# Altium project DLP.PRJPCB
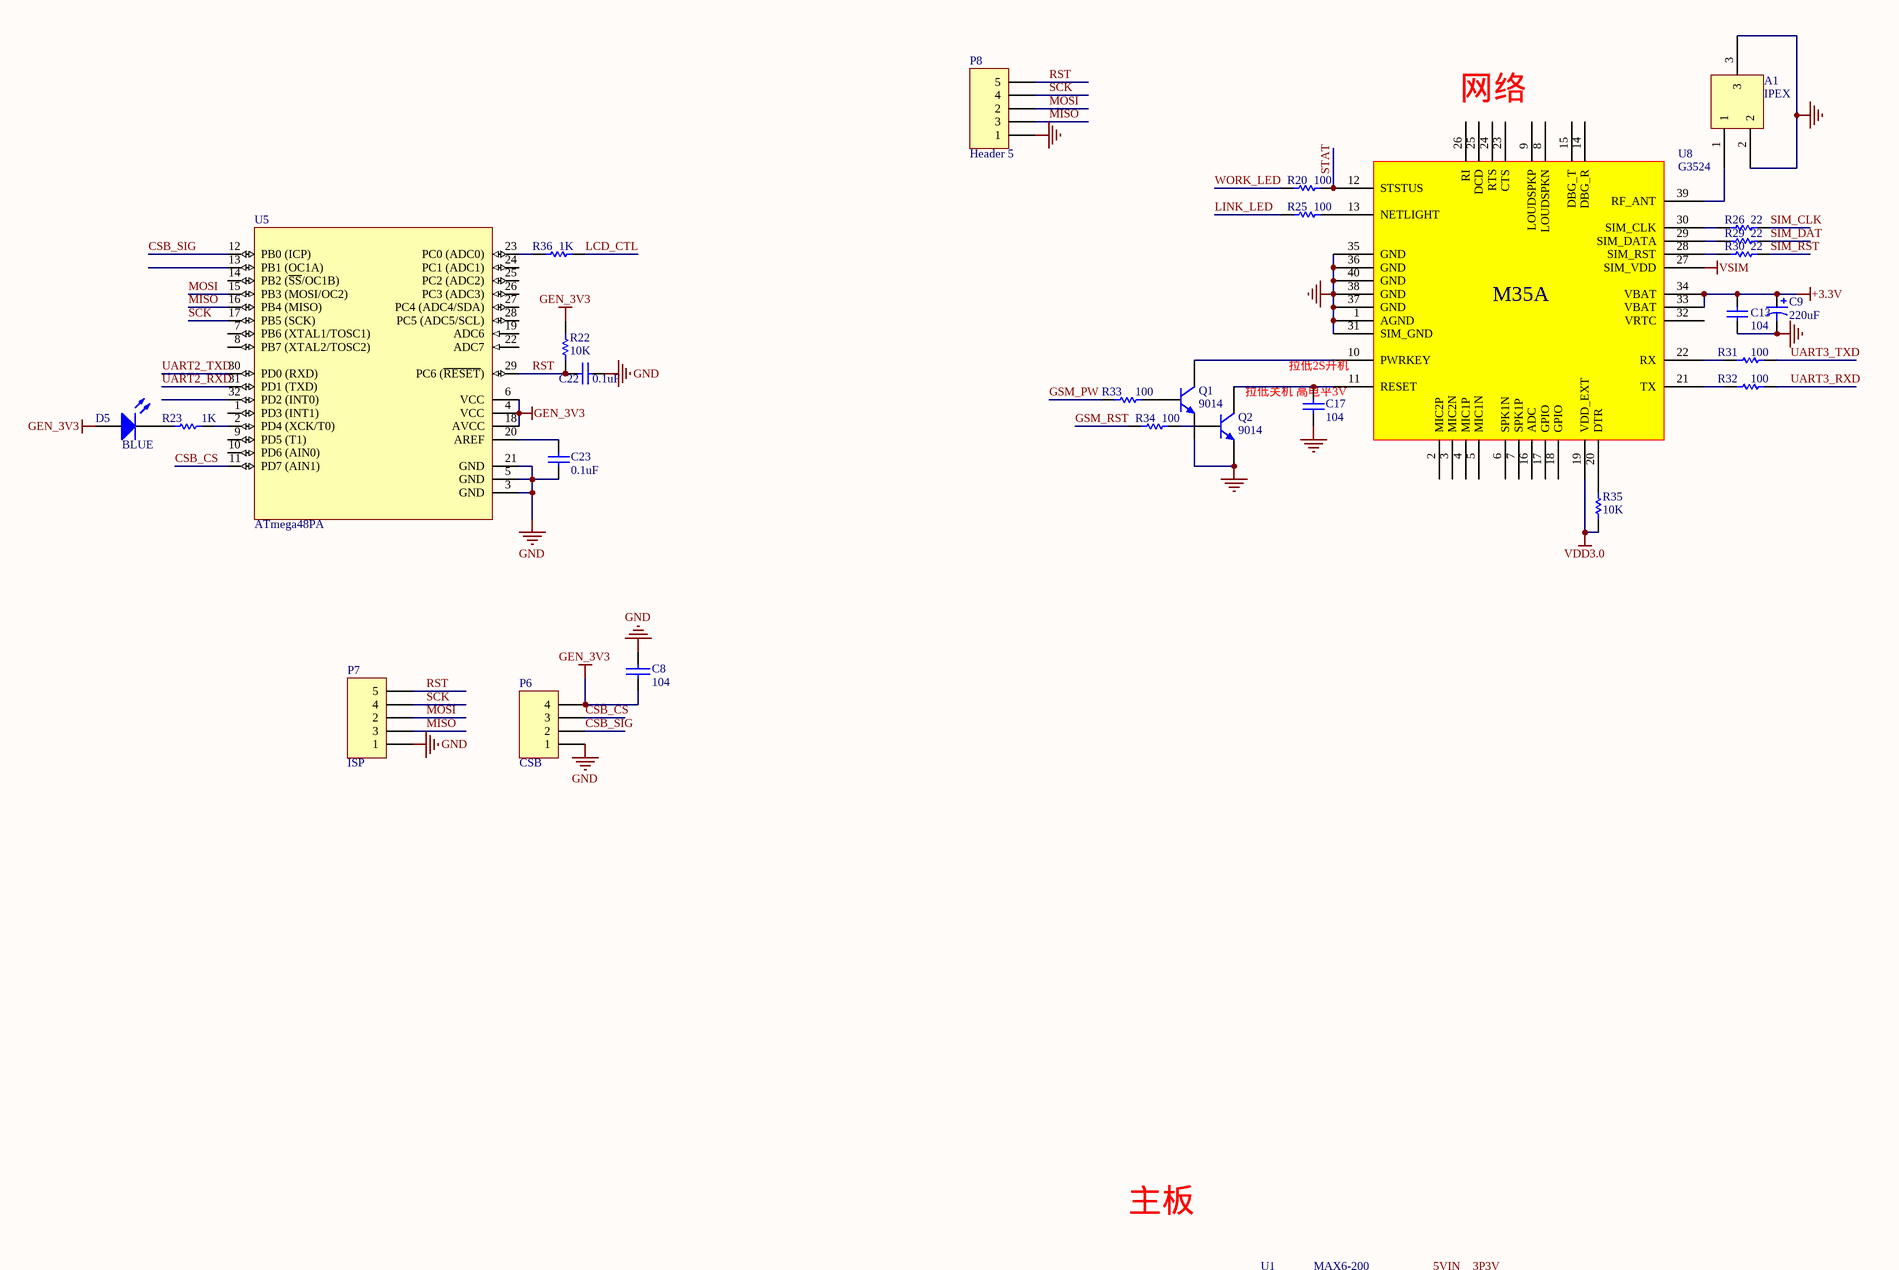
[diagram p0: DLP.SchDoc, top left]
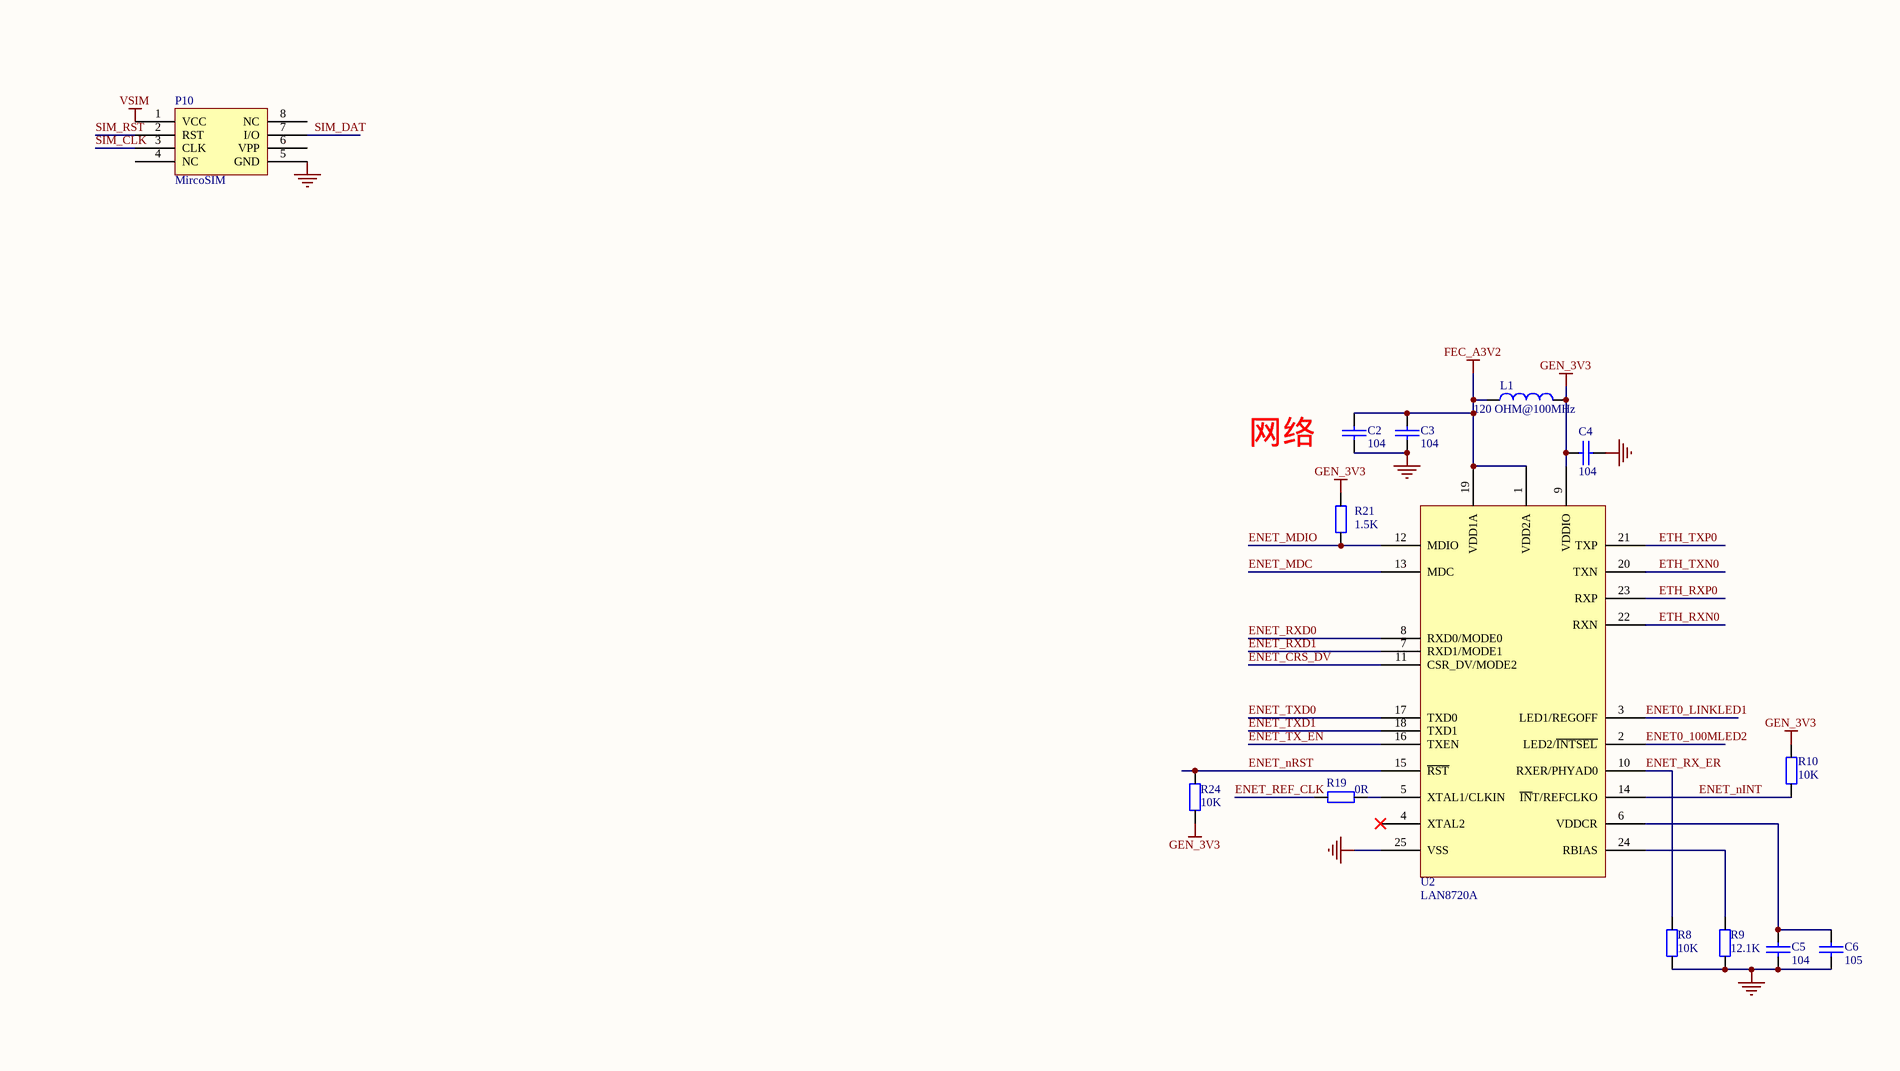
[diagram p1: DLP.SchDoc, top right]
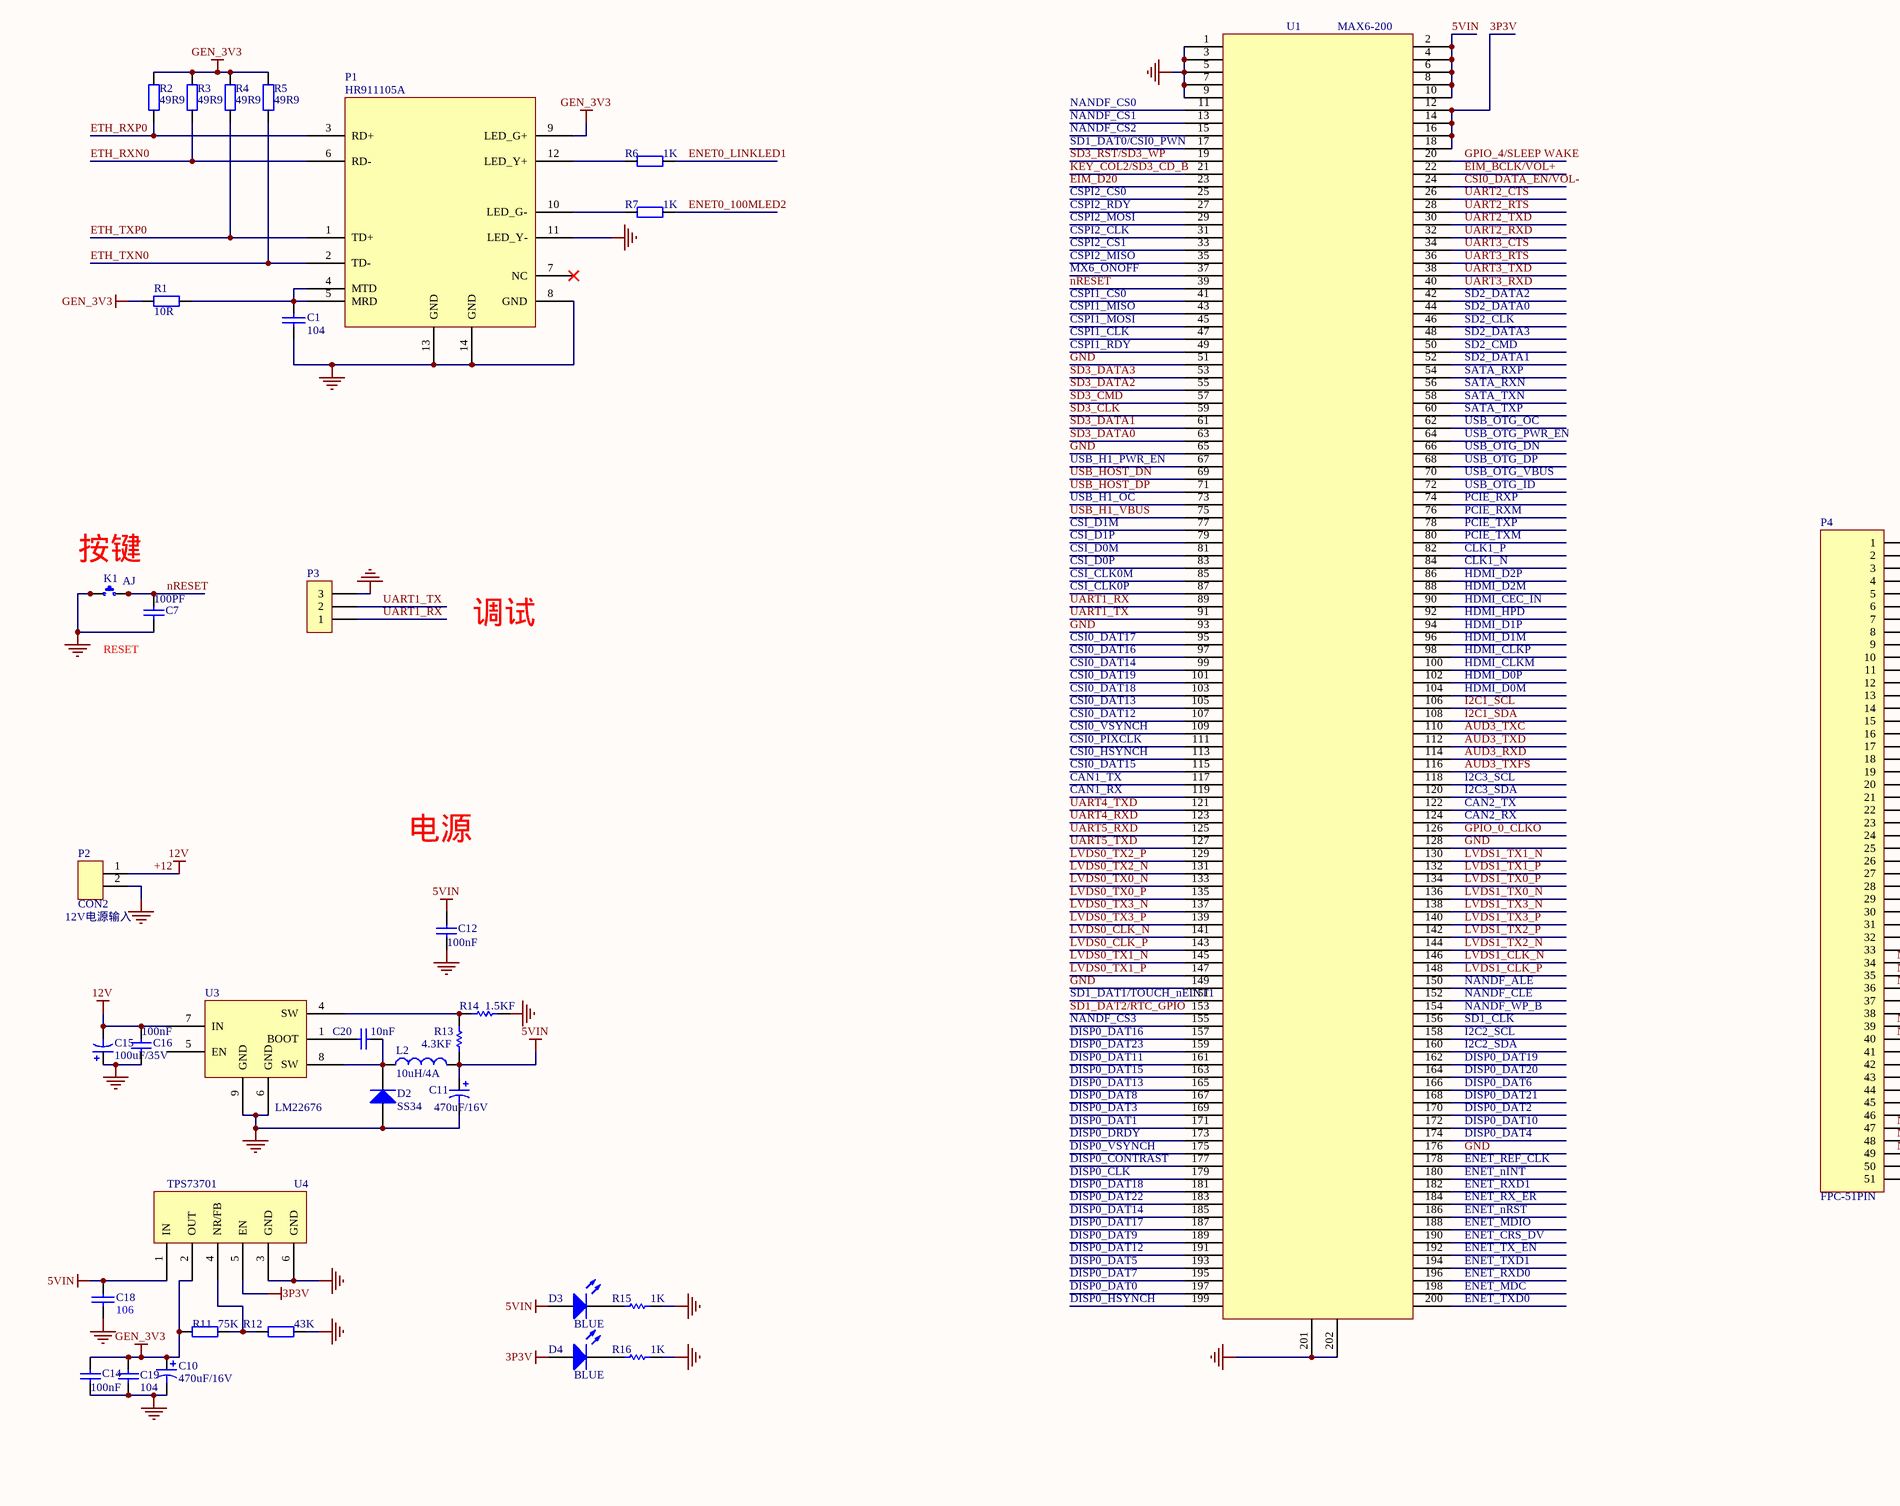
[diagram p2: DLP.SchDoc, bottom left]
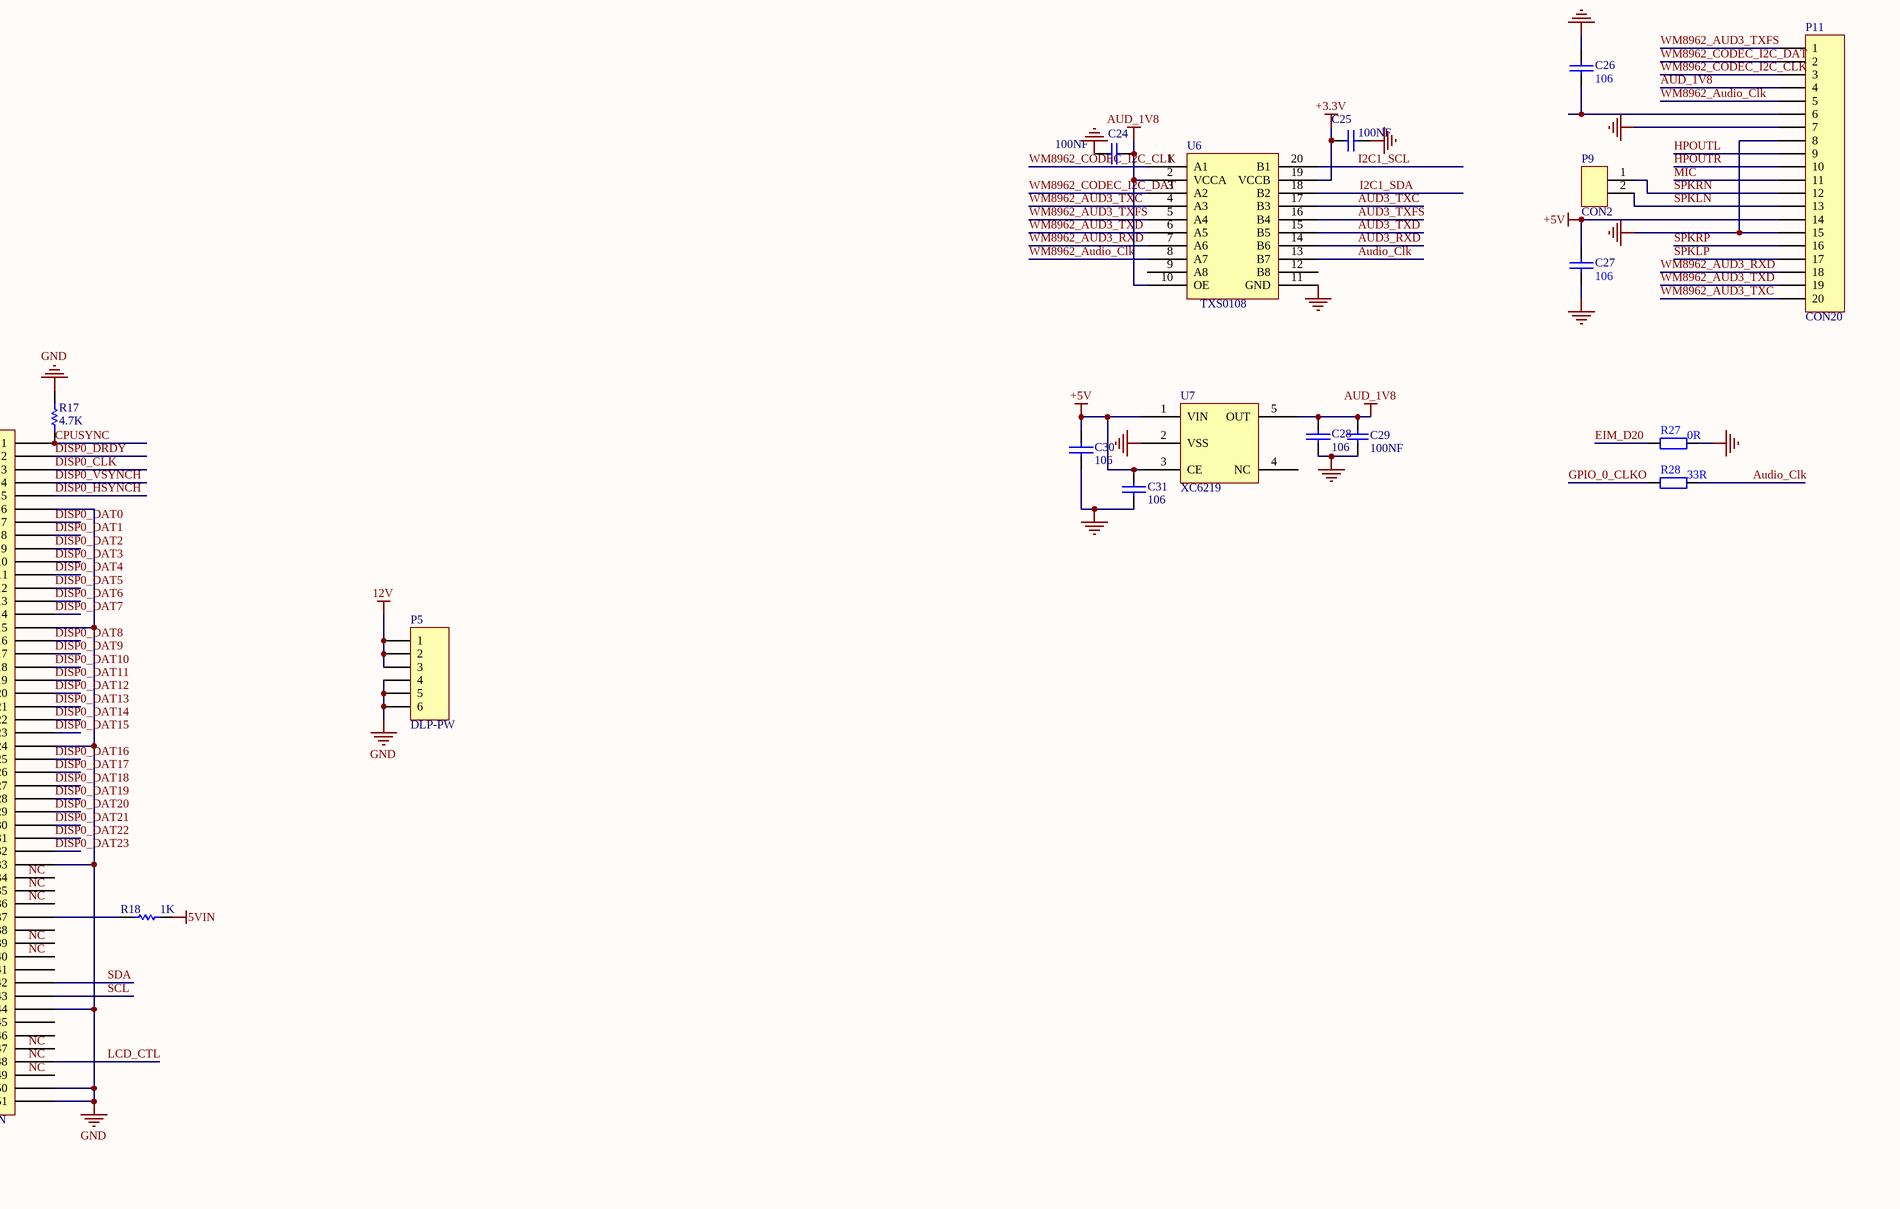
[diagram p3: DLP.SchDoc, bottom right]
1 sheet, 95 parts. Net scope: global (net labels, ports and power ports of the same name join across sheets).
Board file: DLP.PcbDoc

## Sheet DLP.SchDoc
size A1

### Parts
A1  IPEX  [IPEX]
C1  104  [0603]
C2  104  [0603]
C3  104  [0603]
C4  104  [0603]
C5  104  [0603]
C6  105  [0603]
C7  100PF  [0603]
C8  104  [0603]
C9  value 220uF  [C7343]  (hidden comment: Cap Pol3)
C10  470uF/16V  [3216[1206]]
C11  470uF/16V  [C6.3*12]
C12  100nF  [0603]
C13  value 104  [0603]  (hidden comment: Cap)
C14  100nF  [0603]
C15  100uF/35V  [C8x4]
C16  100nF  [0603]
C17  value 104  [0603]  (hidden comment: Cap)
C18  106  [C1206]
C19  104  [0603]
C20  10nF  [0603]
C22  value 0.1uF  [0603]  (hidden comment: Cap)
C23  value 0.1uF  [0603]  (hidden comment: Cap)
C24  100NF  [0603]
C25  100NF  [0603]
C26  106  [0603]
C27  106  [0603]
C28  106  [0603]
C29  100NF  [0603]
C30  106  [0603]
C31  106  [0603]
D2  SS34  [SMA]
D3  BLUE  [0603-LED]
D4  BLUE  [0603-LED]
D5  BLUE  [0603-LED]
K1  AJ  [4*4*1.5]
L1  120 OHM@100MHz  [0603]
L2  10uH/4A  [8040]
P1  HR911105A  [HR911105A]
P2  CON2  [PH2.0-2P]
P3  (no value)  [HDR1X3]
P4  FPC-51PIN  [FH26-51S-0.3SHW]
P5  DLP-PW  [SH1.0-6P]
P6  CSB  [HDR1X4]
P7  ISP  [HDR1X5]
P8  Header 5  [HDR1X5]
P9  CON2  [PH2.0-2P]
P10  MircoSIM  [Micro SIM]
P11  CON20  [WM8962]
Q1  value 9014  [SOT-23-NPN]  (hidden comment: NPN)
Q2  value 9014  [SOT-23-NPN]  (hidden comment: NPN)
R1  10R  [0603]
R2  49R9  [0603]
R3  49R9  [0603]
R4  49R9  [0603]
R5  49R9  [0603]
R6  1K  [0603]
R7  1K  [0603]
R8  10K  [0603]
R9  12.1K  [0603]
R10  10K  [0603]
R11  75K  [0603]
R12  43K  [0603]
R13  4.3KF  [0603]
R14  1.5KF  [0603]
R15  1K  [0603]
R16  1K  [0603]
R17  value 4.7K  [0603]  (hidden comment: Res1)
R18  1K  [0603]
R19  0R  [0603]
R20  value 100  [0603]  (hidden comment: Res1)
R21  1.5K  [0603]
R22  value 10K  [0603]  (hidden comment: Res1)
R23  1K  [0603]
R24  10K  [0603]
R25  value 100  [0603]  (hidden comment: Res1)
R26  value 22  [0603]  (hidden comment: Res1)
R27  0R  [0603]
R28  33R  [0603]
R29  value 22  [0603]  (hidden comment: Res1)
R30  value 22  [0603]  (hidden comment: Res1)
R31  value 100  [0603]  (hidden comment: Res1)
R32  value 100  [0603]  (hidden comment: Res1)
R33  value 100  [0603]  (hidden comment: Res1)
R34  value 100  [0603]  (hidden comment: Res1)
R35  value 10K  [0603]  (hidden comment: Res1)
R36  1K  [0603]
U1  MAX6-200  [SO-DIMM 200]
U2  LAN8720A  [QFN24_4X4MM]
U3  LM22676  [SO-8HP]
U4  TPS73701  [SOT223-6]
U5  ATmega48PA  [32A_M]
U6  TXS0108  [TSSOP-20]
U7  XC6219  [SOT23-5N]
U8  G3524  [G3524]

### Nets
3P3V: D4.1(A) U1.12 U1.14 U1.16 U1.18 U4.5(EN)
5VIN: C11.1 C12.2 C18.1 D3.1(A) L2.2 R13.2 R18.1 U1.2 U1.4 U1.6 U1.8 U1.10 U4.1(IN)
+3.3V: C9.1 C13.2 C25.1 U6.19(VCCB) U8.33(VBAT) U8.34(VBAT)
+5V: C27.2 C30.1 C31.1 P11.14 U7.1(VIN) U7.3(CE)
+12: C15.2 C16.2 P2.1 P5.1 P5.2 P5.3 U3.7(IN)  [also labelled 12V]
AUD_1V8: C24.2 C28.1 C29.1 P11.4 U6.2(VCCA) U6.10(OE) U7.5(OUT)
FEC_A3V2: C2.1 C3.1 L1.1 U2.1(VDD2A) U2.19(VDD1A)
GEN_3V3: C4.2 C8.2 C10.1 C14.2 C19.2 D5.1(A) L1.2 P1.9(LED_G+) P6.4 R1.2 R2.2 R3.2 R4.2 R5.2 R10.2 R11.2 R21.2 R22.2 R24.1 U2.9(VDDIO) U4.2(OUT) U5.4(VCC) U5.6(VCC) U5.18(AVCC)
GND: A1.2 A1.3 C1.2 C2.2 C3.2 C4.1 C5.2 C6.2 C7.1 C8.1 C9.2 C10.2 C11.2 C12.1 C13.1 C14.1 C15.1 C16.1 C17.2 C18.2 C19.1 C22.2 C23.2 C24.1 C25.2 C26.1 C27.1 C28.2 C29.2 C30.2 C31.2 D2.1(A) K1.1 K1.2 P1.8(GND) P1.11(LED_Y-) P1.13(GND) P1.14(GND) P2.2 P3.3 P4.6 P4.15 P4.24 P4.33 P4.44 P4.50 P4.51 P5.4 P5.5 P5.6 P6.1 P7.1 P8.1 P10.5(GND) P11.7 P11.8 P11.15 Q1.1(E) Q2.1(E) R8.1 R9.1 R12.2 R14.2 R15.1 R16.1 R17.1 R27.1 U1.1 U1.3 U1.5 U1.7 U1.9 U1.51 U1.65 U1.93 U1.128 U1.149 U1.176 U1.201 U1.202 U2.25(VSS) U3.6(GND) U3.9(GND) U4.3(GND) U4.6(GND) U5.3(GND) U5.5(GND) U5.21(GND) U6.11(GND) U7.2(VSS) U8.1(AGND) U8.31(SIM_GND) U8.35(GND) U8.36(GND) U8.37(GND) U8.38(GND) U8.40(GND)
VDD3.0: R35.2 U8.19(VDD_EXT)
VSIM: P10.1(VCC) U8.27(SIM_VDD)
AUD3_RXD: U1.114 U6.14(B6)
AUD3_TXC: U1.110 U6.17(B3)
AUD3_TXD: U1.112 U6.15(B5)
AUD3_TXFS: U1.116 U6.16(B4)
Audio_Clk: R28.1 U6.13(B7)
CAN1_RX: U1.119
CAN1_TX: U1.117
CAN2_RX: U1.124
CAN2_TX: U1.122
CLK1_N: U1.84
CLK1_P: U1.82
CPUSYNC: P4.1 R17.2
CSB_CS: P6.3 U5.11(PD7_(AIN1))
CSB_SIG: P6.2 U5.12(PB0_(ICP))
CSI0_DAT12: U1.107
CSI0_DAT13: U1.105
CSI0_DAT14: U1.99
CSI0_DAT15: U1.115
CSI0_DAT16: U1.97
CSI0_DAT17: U1.95
CSI0_DAT18: U1.103
CSI0_DAT19: U1.101
CSI0_DATA_EN/VOL-: U1.24
CSI0_HSYNCH: U1.113
CSI0_PIXCLK: U1.111
CSI0_VSYNCH: U1.109
CSI_CLK0M: U1.85
CSI_CLK0P: U1.87
CSI_D0M: U1.81
CSI_D0P: U1.83
CSI_D1M: U1.77
CSI_D1P: U1.79
CSPI1_CLK: U1.47
CSPI1_CS0: U1.41
CSPI1_MISO: U1.43
CSPI1_MOSI: U1.45
CSPI1_RDY: U1.49
CSPI2_CLK: U1.31
CSPI2_CS0: U1.25
CSPI2_CS1: U1.33
CSPI2_MISO: U1.35
CSPI2_MOSI: U1.29
CSPI2_RDY: U1.27
DISP0_CLK: P4.3 U1.179
DISP0_CONTRAST: U1.177
DISP0_DAT0: P4.7 U1.197
DISP0_DAT1: P4.8 U1.171
DISP0_DAT2: P4.9 U1.170
DISP0_DAT3: P4.10 U1.169
DISP0_DAT4: P4.11 U1.174
DISP0_DAT5: P4.12 U1.193
DISP0_DAT6: P4.13 U1.166
DISP0_DAT7: P4.14 U1.195
DISP0_DAT8: P4.16 U1.167
DISP0_DAT9: P4.17 U1.189
DISP0_DAT10: P4.18 U1.172
DISP0_DAT11: P4.19 U1.161
DISP0_DAT12: P4.20 U1.191
DISP0_DAT13: P4.21 U1.165
DISP0_DAT14: P4.22 U1.185
DISP0_DAT15: P4.23 U1.163
DISP0_DAT16: P4.25 U1.157
DISP0_DAT17: P4.26 U1.187
DISP0_DAT18: P4.27 U1.181
DISP0_DAT19: P4.28 U1.162
DISP0_DAT20: P4.29 U1.164
DISP0_DAT21: P4.30 U1.168
DISP0_DAT22: P4.31 U1.183
DISP0_DAT23: P4.32 U1.159
DISP0_DRDY: P4.2 U1.173
DISP0_HSYNCH: P4.5 U1.199
DISP0_VSYNCH: P4.4 U1.175
EIM_BCLK/VOL+: U1.22
EIM_D20: R27.2 U1.23
ENET0_100MLED2: R7.2 U2.2(LED2/~{INTSEL})
ENET0_LINKLED1: R6.2 U2.3(LED1/REGOFF)
ENET_CRS_DV: U1.190 U2.11(CSR_DV/MODE2)
ENET_MDC: U1.198 U2.13(MDC)
ENET_MDIO: R21.1 U1.188 U2.12(MDIO)
ENET_nINT: R10.1 U1.180 U2.14(~{IN}T/REFCLKO)
ENET_nRST: R24.2 U1.186 U2.15(~{RST})
ENET_REF_CLK: R19.2 U1.178
ENET_RX_ER: R8.2 U1.184 U2.10(RXER/PHYAD0)
ENET_RXD0: U1.196 U2.8(RXD0/MODE0)
ENET_RXD1: U1.182 U2.7(RXD1/MODE1)
ENET_TX_EN: U1.192 U2.16(TXEN)
ENET_TXD0: U1.200 U2.17(TXD0)
ENET_TXD1: U1.194 U2.18(TXD1)
ETH_RXN0: P1.6(RD-) R3.1 U2.22(RXN)
ETH_RXP0: P1.3(RD+) R2.1 U2.23(RXP)
ETH_TXN0: P1.2(TD-) R5.1 U2.20(TXN)
ETH_TXP0: P1.1(TD+) R4.1 U2.21(TXP)
GPIO_0_CLKO: R28.2 U1.126
GPIO_4/SLEEP WAKE: U1.20
GSM_PW: R33.2
GSM_RST: R34.2
HDMI_CEC_IN: U1.90
HDMI_CLKM: U1.100
HDMI_CLKP: U1.98
HDMI_D0M: U1.104
HDMI_D0P: U1.102
HDMI_D1M: U1.96
HDMI_D1P: U1.94
HDMI_D2M: U1.88
HDMI_D2P: U1.86
HDMI_HPD: U1.92
HPOUTL: P11.9
HPOUTR: P11.10
I2C1_SCL: U1.106 U6.20(B1)
I2C1_SDA: U1.108 U6.18(B2)
I2C2_SCL: U1.158
I2C2_SDA: U1.160
I2C3_SCL: U1.118
I2C3_SDA: U1.120
KEY_COL2/SD3_CD_B: U1.21
LCD_CTL: P4.48 R36.1
LINK_LED: R25.2
LVDS0_CLK_N: U1.141
LVDS0_CLK_P: U1.143
LVDS0_TX0_N: U1.133
LVDS0_TX0_P: U1.135
LVDS0_TX1_N: U1.145
LVDS0_TX1_P: U1.147
LVDS0_TX2_N: U1.131
LVDS0_TX2_P: U1.129
LVDS0_TX3_N: U1.137
LVDS0_TX3_P: U1.139
LVDS1_CLK_N: U1.146
LVDS1_CLK_P: U1.148
LVDS1_TX0_N: U1.136
LVDS1_TX0_P: U1.134
LVDS1_TX1_N: U1.130
LVDS1_TX1_P: U1.132
LVDS1_TX2_N: U1.144
LVDS1_TX2_P: U1.142
LVDS1_TX3_N: U1.138
LVDS1_TX3_P: U1.140
MIC: P11.11
MISO: P7.3 P8.3 U5.16(PB4_(MISO))
MOSI: P7.2 P8.2 U5.15(PB3_(MOSI/OC2))
MX6_ONOFF: U1.37
NANDF_ALE: U1.150
NANDF_CLE: U1.152
NANDF_CS0: U1.11
NANDF_CS1: U1.13
NANDF_CS2: U1.15
NANDF_CS3: U1.155
NANDF_WP_B: U1.154
nRESET: C7.2 K1.3 K1.4 U1.39
PCIE_RXM: U1.76
PCIE_RXP: U1.74
PCIE_TXM: U1.80
PCIE_TXP: U1.78
RST: C22.1 P7.5 P8.5 R22.1 U5.29(PC6_(~{RESET}))
SATA_RXN: U1.56
SATA_RXP: U1.54
SATA_TXN: U1.58
SATA_TXP: U1.60
SCK: P7.4 P8.4 U5.17(PB5_(SCK))
SCL: P4.43
SD1_CLK: U1.156
SD1_DAT0/CSI0_PWN: U1.17
SD1_DAT1/TOUCH_nEINT1: U1.151
SD1_DAT2/RTC_GPIO: U1.153
SD2_CLK: U1.46
SD2_CMD: U1.50
SD2_DATA0: U1.44
SD2_DATA1: U1.52
SD2_DATA2: U1.42
SD2_DATA3: U1.48
SD3_CLK: U1.59
SD3_CMD: U1.57
SD3_DATA0: U1.63
SD3_DATA1: U1.61
SD3_DATA2: U1.55
SD3_DATA3: U1.53
SD3_RST/SD3_WP: U1.19
SDA: P4.42
SIM_CLK: P10.3(CLK) R26.1
SIM_DAT: P10.7(I/O) R29.1
SIM_RST: P10.2(RST) R30.1
SPKLN: P9.2 P11.13
SPKLP: P11.17
SPKRN: P9.1 P11.12
SPKRP: P11.16
STAT: R20.1 U8.12(STSTUS)
UART1_RX: P3.1 U1.89
UART1_TX: P3.2 U1.91
UART2_CTS: U1.26
UART2_RTS: U1.28
UART2_RXD: U1.32 U5.31(PD1_(TXD))
UART2_TXD: U1.30 U5.30(PD0_(RXD))
UART3_CTS: U1.34
UART3_RTS: U1.36
UART3_RXD: R32.2 U1.40
UART3_TXD: R31.2 U1.38
UART4_RXD: U1.123
UART4_TXD: U1.121
UART5_RXD: U1.125
UART5_TXD: U1.127
USB_H1_OC: U1.73
USB_H1_PWR_EN: U1.67
USB_H1_VBUS: U1.75
USB_HOST_DN: U1.69
USB_HOST_DP: U1.71
USB_OTG_DN: U1.66
USB_OTG_DP: U1.68
USB_OTG_ID: U1.72
USB_OTG_OC: U1.62
USB_OTG_PWR_EN: U1.64
USB_OTG_VBUS: U1.70
WM8962_AUD3_RXD: P11.18 U6.7(A6)
WM8962_AUD3_TXC: P11.20 U6.4(A3)
WM8962_AUD3_TXD: P11.19 U6.6(A5)
WM8962_AUD3_TXFS: P11.1 U6.5(A4)
WM8962_Audio_Clk: P11.5 U6.8(A7)
WM8962_CODEC_I2C_CLK: P11.3 U6.1(A1)
WM8962_CODEC_I2C_DAT: P11.2 U6.3(A2)
WORK_LED: R20.2
NetA1_1: A1.1 U8.39(RF_ANT)
NetC1_1: C1.1 P1.4(MTD) P1.5(MRD) R1.1
NetC5_1: C5.1 C6.1 U2.6(VDDCR)
NetC17_1: C17.1 Q2.3(C) U8.11(RESET)
NetC20_1: C20.1 D2.2(K) L2.1 U3.8(SW)
NetC20_2: C20.2 U3.1(BOOT)
NetC23_1: C23.1 U5.20(AREF)
NetC26_2: C26.2 P11.6
NetD3_2: D3.2(K) R15.2
NetD4_2: D4.2(K) R16.2
NetD5_2: D5.2(K) R23.2
NetP1_10: P1.10(LED_G-) R7.1
NetP1_12: P1.12(LED_Y+) R6.1
NetP4_37: P4.37 R18.2
NetQ1_2: Q1.2(B) R33.1
NetQ1_3: Q1.3(C) U8.10(PWRKEY)
NetQ2_2: Q2.2(B) R34.1
NetR9_2: R9.2 U2.24(RBIAS)
NetR11_1: R11.1 R12.1 U4.4(NR/FB)
NetR13_1: R13.1 R14.1 U3.4(SW)
NetR19_1: R19.1 U2.5(XTAL1/CLKIN)
NetR23_1: R23.1 U5.2(PD4_(XCK/T0))
NetR25_1: R25.1 U8.13(NETLIGHT)
NetR26_2: R26.2 U8.30(SIM_CLK)
NetR29_2: R29.2 U8.29(SIM_DATA)
NetR30_2: R30.2 U8.28(SIM_RST)
NetR31_1: R31.1 U8.22(RX)
NetR32_1: R32.1 U8.21(TX)
NetR35_1: R35.1 U8.20(DTR)
NetR36_2: R36.2 U5.23(PC0_(ADC0))

Not connected (* = marked no-connect by the designer): P1 7(NC)*; P4 34 35 36 38 39 40 41 45 46 47 49; P10 4(NC) 6(VPP) 8(NC); U2 4(XTAL2)*; U3 5(EN); U5 1(PD3_(INT1)) 7(PB6_(XTAL1/TOSC1)) 8(PB7_(XTAL2/TOSC2)) 9(PD5_(T1)) 10(PD6_(AIN0)) 13(PB1_(OC1A)) 14(PB2_(~{SS}/OC1B)) 19(ADC6) 22(ADC7) 24(PC1_(ADC1)) 25(PC2_(ADC2)) 26(PC3_(ADC3)) 27(PC4_(ADC4/SDA)) 28(PC5_(ADC5/SCL)) 32(PD2_(INT0)); U6 9(A8) 12(B8); U7 4(NC); U8 2(MIC2P) 3(MIC2N) 4(MIC1P) 5(MIC1N) 6(SPK1N) 7(SPK1P) 8(LOUDSPKN) 9(LOUDSPKP) 14(DBG_R) 15(DBG_T) 16(ADC) 17(GPIO) 18(GPIO) 23(CTS) 24(RTS) 25(DCD) 26(RI) 32(VRTC)

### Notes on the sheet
- 网络
- 拉低关机 高电平3V
- (near C17) 拉低2S开机
- 主板
- (near K1) 按键
- RESET
- 调试
- 电源
- (near P2) 12V电源输入
- Labels drawn without touching a wire or pin: NC

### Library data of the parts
C1-C6 C8 C18 C26-C28 C30 C31 = CAP
C7 C12-C14 C16 C17 C20 C22 C23 = Cap: Capacitor
C9 = Cap Pol3: Polarized Capacitor (Surface Mount)
C10 C11 C15 = Cap Pol1: Polarized Capacitor (Radial)
C19 C24 C25 C29 = Cap
D2 = Diode 1N5408: 3 Amp Medium Power Silicon Rectifier Diode
D3-D5 = LED2: Typical RED, GREEN, YELLOW, AMBER GaAs LED
K1 = KEY_1
L1 L2 = Inductor
P3 = CON3: Connector
P5 = Header 6: Header, 6-Pin
P6 = Header 4: Header, 4-Pin
P7 P8 = Header 5: Header, 5-Pin
Q1 Q2 = 2N5551: NPN General Purpose Amplifier
R1-R10 R19 R21 R24 R27 R28 = RES
R11 R12 = Res2: Resistor
R13-R18 R20 R22 R23 R25 R26 R29-R36 = Res1: Resistor
U4 = TPS737
U5 = ATmega8-16AC: 8-Bit AVR Microcontroller with 8K Bytes of In-System Programmable Flash Memory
